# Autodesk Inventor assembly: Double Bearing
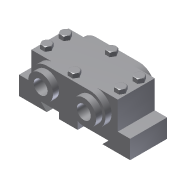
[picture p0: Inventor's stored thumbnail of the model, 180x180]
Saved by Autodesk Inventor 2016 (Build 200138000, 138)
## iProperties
Shininess: 64.0
Length Units: 11269
Angle Units: 11279
Time Units: 11290
Mass Units: 11283
Length Display Precision: 3
Angle Display Precision: 2
Created: 2002-02
Part Number: Double Bearing
Document SubType Name: Assembly
Designer: ***
Density: 0.0
Volumn: 0.0
Area: 0.0
PropertySet Name: Model Information
Control State: 0
Master: False
Checked Out: False
Author: ***
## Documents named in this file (5)
- D:\KAVITA\Autodesk Inventor_ 2016 Project_Kavita\Inventor_Part Files\Inventor_2016_Part\c12_Inv_2016\c12_inv_2016_prt\fig-12-10 and 12-18\Double Bearing.iam
- D:\KAVITA\Autodesk Inventor_ 2016 Project_Kavita\Inventor_Part Files\Inventor_2016_Part\c12_Inv_2016\c12_inv_2016_prt\fig-12-10 and 12-18\Base.ipt
- D:\KAVITA\Autodesk Inventor_ 2016 Project_Kavita\Inventor_Part Files\Inventor_2016_Part\c12_Inv_2016\c12_inv_2016_prt\fig-12-10 and 12-18\Cap.ipt
- D:\KAVITA\Autodesk Inventor_ 2016 Project_Kavita\Inventor_Part Files\Inventor_2016_Part\c12_Inv_2016\c12_inv_2016_prt\fig-12-10 and 12-18\Bushing.ipt
- D:\KAVITA\Autodesk Inventor_ 2016 Project_Kavita\Inventor_Part Files\Inventor_2016_Part\c12_Inv_2016\c12_inv_2016_prt\fig-12-10 and 12-18\Bolt.ipt
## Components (10 placed, 4 different names)
1. Base:1 — Insert:1, Insert:2
2. Cap:1 — Insert:1, Insert:2, Insert:3, Insert:4, Insert:5, Insert:6
3. Bushing:1 — Insert:3
4. Bushing:2 — Insert:4
5. Bolt:1 — Insert:5
6. Bolt:6
7. Bolt:7
8. Bolt:8
9. Bolt:5 — Insert:6
10. Bolt:9
## Component patterns: Component Pattern 1 (4 elements), Component Pattern 2 (2 elements)
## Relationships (6: Insert 6)
- Insert:1: Base:1 ↔ Cap:1
- Insert:2: Base:1 ↔ Cap:1
- Insert:3: Cap:1 ↔ Bushing:1
- Insert:4: Cap:1 ↔ Bushing:2
- Insert:5: Cap:1 ↔ Bolt:1
- Insert:6: Cap:1 ↔ Bolt:5
